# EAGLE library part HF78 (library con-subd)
SUB-D
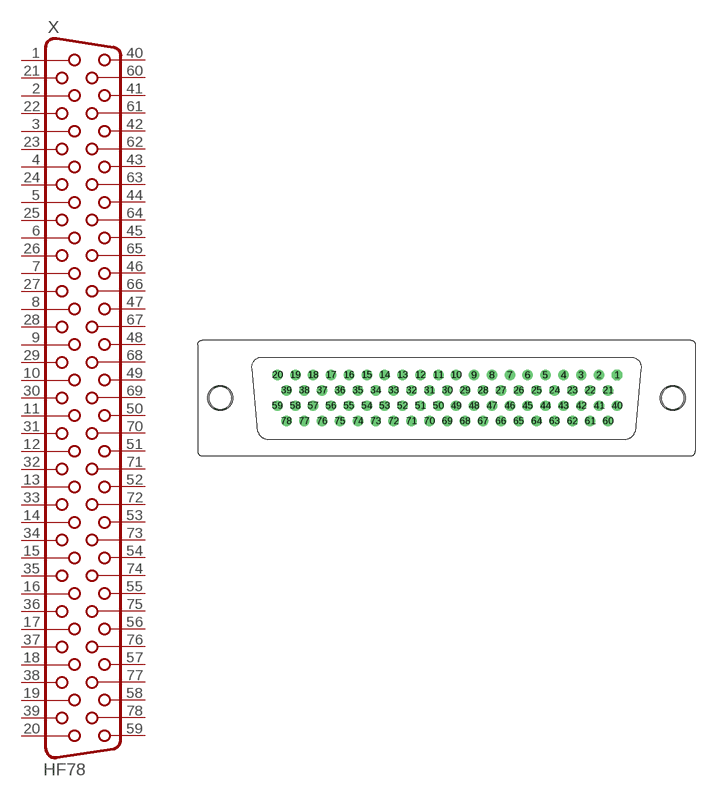
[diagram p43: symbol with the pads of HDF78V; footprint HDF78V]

Designator prefix X

## HF78V (OC_FARNELL: unknown; OC_NEWARK: unknown)  [HDF78V]
1  1  pas
2  2  pas
3  3  pas
4  4  pas
5  5  pas
6  6  pas
7  7  pas
8  8  pas
9  9  pas
10  10  pas
11  11  pas
12  12  pas
13  13  pas
14  14  pas
15  15  pas
16  16  pas
17  17  pas
18  18  pas
19  19  pas
20  20  pas
21  21  pas
22  22  pas
23  23  pas
24  24  pas
25  25  pas
26  26  pas
27  27  pas
28  28  pas
29  29  pas
30  30  pas
31  31  pas
32  32  pas
33  33  pas
34  34  pas
35  35  pas
36  36  pas
37  37  pas
38  38  pas
39  39  pas
40  40  pas
41  41  pas
42  42  pas
43  43  pas
44  44  pas
45  45  pas
46  46  pas
47  47  pas
48  48  pas
49  49  pas
50  50  pas
51  51  pas
52  52  pas
53  53  pas
54  54  pas
55  55  pas
56  56  pas
57  57  pas
58  58  pas
59  59  pas
60  60  pas
61  61  pas
62  62  pas
63  63  pas
64  64  pas
65  65  pas
66  66  pas
67  67  pas
68  68  pas
69  69  pas
70  70  pas
71  71  pas
72  72  pas
73  73  pas
74  74  pas
75  75  pas
76  76  pas
77  77  pas
78  78  pas

## Footprint HDF78V (pad centres in mm)
SUB-D
drill 0.9 octagon: 1 23.024,3.12
drill 0.9 round: 2 20.611,3.12; 3 18.198,3.12; 4 15.785,3.12; 5 13.372,3.12; 6 10.959,3.12; 7 8.546,3.12; 8 6.133,3.12; 9 3.72,3.12; 10 1.307,3.12; 11 -1.106,3.12; 12 -3.519,3.12; 13 -5.932,3.12; 14 -8.345,3.12; 15 -10.758,3.12; 16 -13.171,3.12; 17 -15.584,3.12; 18 -17.997,3.12; 19 -20.41,3.12; 20 -22.823,3.12; 21 21.817,1.04; 22 19.404,1.04; 23 16.991,1.04; 24 14.578,1.04; 25 12.165,1.04; 26 9.752,1.04; 27 7.339,1.04; 28 4.926,1.04; 29 2.513,1.04; 30 0.1,1.04; 31 -2.313,1.04; 32 -4.726,1.04; 33 -7.139,1.04; 34 -9.552,1.04; 35 -11.965,1.04; 36 -14.378,1.04; 37 -16.791,1.04; 38 -19.204,1.04; 39 -21.617,1.04; 40 23.024,-1.04; 41 20.611,-1.04; 42 18.198,-1.04; 43 15.785,-1.04; 44 13.372,-1.04; 45 10.959,-1.04; 46 8.546,-1.04; 47 6.133,-1.04; 48 3.72,-1.04; 49 1.307,-1.04; 50 -1.106,-1.04; 51 -3.519,-1.04; 52 -5.932,-1.04; 53 -8.345,-1.04; 54 -10.758,-1.04; 55 -13.171,-1.04; 56 -15.584,-1.04; 57 -17.997,-1.04; 58 -20.41,-1.04; 59 -22.823,-1.04; 60 21.817,-3.12; 61 19.404,-3.12; 62 16.991,-3.12; 63 14.578,-3.12; 64 12.165,-3.12; 65 9.752,-3.12; 66 7.339,-3.12; 67 4.926,-3.12; 68 2.513,-3.12; 69 0.1,-3.12; 70 -2.313,-3.12; 71 -4.726,-3.12; 72 -7.139,-3.12; 73 -9.552,-3.12; 74 -11.965,-3.12; 75 -14.378,-3.12; 76 -16.791,-3.12; 77 -19.204,-3.12; 78 -21.617,-3.12
hole 3 at -30.55,0
hole 3 at 30.55,0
